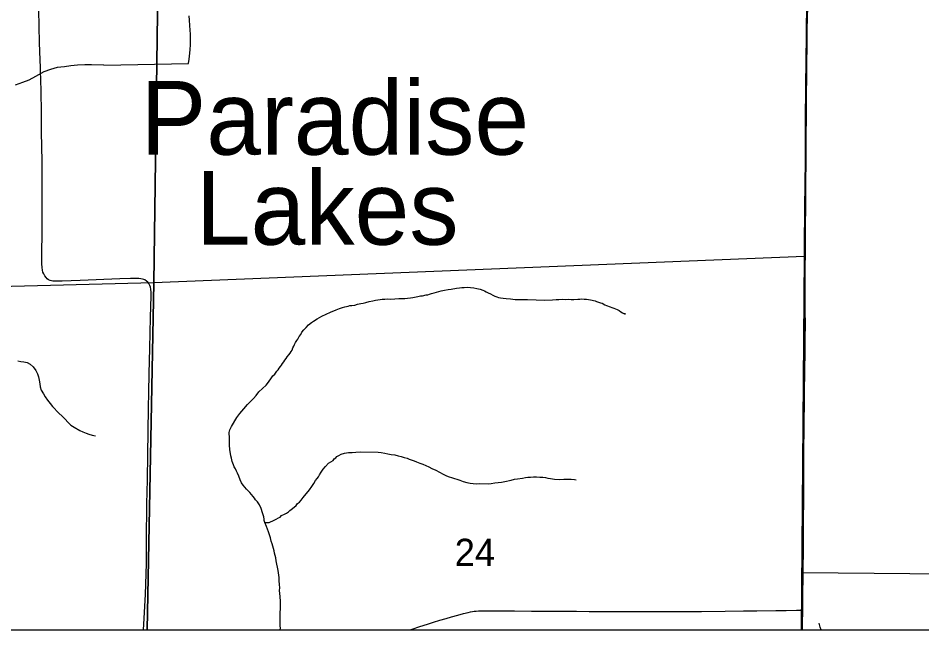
# Model space of a CAD drawing. Extents: x 0 to 34, y 0 to 22.
# Drawn here: x 29.433 to 30.131, y 13.436 to 13.908 of the extents above; entities that cross this region are included whole.
import ezdxf

# ---------------------------------------------------------------- set-up
doc = ezdxf.new("R2010")
doc.units = 0
for name, color, linetype in [('GM_X_County_Road', 7, 'Continuous'), ('GM_X_Minor_Lake_Text', 7, 'Continuous'), ('GM_X_Minor_River', 7, 'Continuous'), ('GM_X_Section', 7, 'Continuous'), ('GM_X_Section_Text', 7, 'Continuous'), ('GM_X_Township_Road', 7, 'Continuous'), ('GM_X_Unincorporated', 7, 'Continuous'), ('SC_Scratch1', 7, 'Continuous'), ('SH_Border', 7, 'Continuous'), ('SH_Cut_Line', 7, 'Continuous')]:
    doc.layers.add(name, color=color, linetype=linetype)

msp = doc.modelspace()

# ---------------------------------------------------------------- linework, layer by layer
at = {"layer": 'GM_X_County_Road'}
for points in [[(30.03851, 13.4804), (30.03866, 13.48736), (30.03866, 13.49255), (30.03877, 13.50555), (30.03886, 13.52261), (30.03893, 13.53385), (30.03897, 13.54364), (30.03899, 13.54923), (30.03899, 13.56171), (30.0391, 13.5728), (30.03925, 13.59278), (30.03934, 13.5985), (30.0394, 13.60898), (30.03929, 13.61489), (30.03938, 13.61848), (30.03951, 13.62533), (30.03957, 13.62941), (30.03979, 13.63852), (30.03987, 13.64802), (30.04002, 13.65739), (30.04002, 13.67502), (30.04001, 13.67906), (30.03998, 13.68927), (30.03996, 13.6975), (30.03994, 13.70491), (30.04005, 13.71657), (30.04007, 13.72566), (30.04009, 13.73357), (30.04013, 13.74223), (30.04024, 13.75149), (30.04032, 13.75843), (30.04052, 13.78374), (30.04071, 13.79487), (30.04069, 13.80748), (30.04078, 13.82039), (30.04082, 13.82804), (30.04091, 13.83689), (30.0411, 13.84759), (30.04105, 13.85861), (30.04119, 13.87305), (30.04123, 13.87844), (30.04146, 13.89213), (30.04159, 13.89971), (30.04185, 13.91691)], [(30.03851, 13.4804), (30.12122, 13.47968), (30.19869, 13.47902), (30.32696, 13.47856), (30.57905, 13.47654), (30.66094, 13.47675), (30.67161, 13.4767), (30.6765, 13.47718), (30.68129, 13.47801), (30.68597, 13.47965), (30.69999, 13.48655)], [(30.03819, 13.45143), (30.03817, 13.4531), (30.0382, 13.46083), (30.03831, 13.46582), (30.03846, 13.47453), (30.03851, 13.4804)], [(29.73532, 13.43613), (29.73729, 13.43678), (29.74321, 13.43875), (29.74907, 13.44065), (29.75369, 13.44211), (29.75856, 13.44356), (29.76333, 13.44496), (29.76757, 13.44619), (29.77255, 13.44761), (29.77678, 13.44875), (29.7805, 13.44967), (29.78226, 13.45007), (29.78386, 13.45037), (29.78517, 13.45055), (29.7866, 13.45072), (29.78833, 13.45082), (29.78981, 13.45088), (29.79148, 13.45095), (29.7935, 13.45095), (29.79669, 13.45096), (29.80326, 13.45091), (29.81621, 13.45081), (29.82927, 13.45072), (29.84549, 13.45062), (29.86405, 13.45051), (29.87388, 13.45042), (29.88577, 13.45032), (29.8983, 13.45027), (29.91267, 13.45026), (29.92829, 13.45031), (29.9416, 13.45036), (29.96045, 13.45043), (29.97883, 13.45057), (29.99296, 13.45076), (30.00317, 13.4509), (30.01791, 13.45111), (30.02598, 13.45124), (30.03394, 13.45137), (30.03819, 13.45143)], [(30.03797, 13.43613), (30.03799, 13.43997), (30.03819, 13.45143)]]:
    msp.add_lwpolyline(points, dxfattribs=at)
at = {"layer": 'GM_X_Minor_River'}
for points in [[(29.49915, 13.8721), (29.56469, 13.87318), (29.56512, 13.87659), (29.56557, 13.88114), (29.5658, 13.88399), (29.56605, 13.88778), (29.56617, 13.89595), (29.56583, 13.89899), (29.5657, 13.9026), (29.56538, 13.90679), (29.56505, 13.91002)], [(29.49915, 13.8721), (29.48976, 13.87236), (29.48445, 13.87232), (29.47894, 13.87209), (29.4738, 13.87148), (29.46884, 13.87067), (29.46314, 13.87026), (29.45816, 13.86869), (29.45299, 13.86674), (29.44644, 13.86332), (29.44142, 13.86042), (29.43644, 13.85866), (29.43069, 13.85654)], [(29.61678, 13.61716), (29.61894, 13.61995), (29.6244, 13.6251), (29.62558, 13.62639), (29.62677, 13.62807), (29.62815, 13.62992), (29.62973, 13.63215), (29.63129, 13.63363), (29.63288, 13.63586), (29.63386, 13.63697), (29.63466, 13.63827), (29.63564, 13.63938), (29.63643, 13.6405), (29.63723, 13.6418), (29.63822, 13.6431), (29.63901, 13.64441), (29.64, 13.64571), (29.64079, 13.64682), (29.64197, 13.64831), (29.64296, 13.64961), (29.64376, 13.65091), (29.64455, 13.65203), (29.64518, 13.65391), (29.64597, 13.65521), (29.64639, 13.65634), (29.6472, 13.65802), (29.64819, 13.65951), (29.64898, 13.66063), (29.64999, 13.6625), (29.65117, 13.66417), (29.65217, 13.66585), (29.65355, 13.66771), (29.65532, 13.66955), (29.65727, 13.67158), (29.65941, 13.67342), (29.66115, 13.6745), (29.66386, 13.67632), (29.66559, 13.67722), (29.66752, 13.6783), (29.67405, 13.68133), (29.67865, 13.68309), (29.68114, 13.68415), (29.68344, 13.68503), (29.68516, 13.68536), (29.68783, 13.68604), (29.68917, 13.68638), (29.69069, 13.68652), (29.69297, 13.68683), (29.69508, 13.68753), (29.69755, 13.68802), (29.69946, 13.68834), (29.70156, 13.68885), (29.70404, 13.68953), (29.7069, 13.69021), (29.70899, 13.69052), (29.71242, 13.69118), (29.71394, 13.69132), (29.71603, 13.69145), (29.71831, 13.69157), (29.72077, 13.6915), (29.72381, 13.69178), (29.72684, 13.69188), (29.72931, 13.692), (29.73158, 13.69193), (29.73367, 13.69224), (29.73595, 13.69255), (29.73766, 13.69269), (29.74166, 13.69333), (29.74357, 13.69384), (29.74528, 13.69398), (29.74795, 13.69466), (29.74928, 13.69481), (29.75062, 13.69515), (29.75215, 13.69567), (29.75425, 13.69636), (29.7596, 13.69772), (29.76208, 13.69841), (29.76494, 13.69889), (29.76722, 13.6992), (29.77141, 13.69983), (29.77369, 13.70014), (29.77559, 13.70046), (29.7773, 13.70041), (29.77957, 13.70053), (29.78222, 13.70045), (29.78487, 13.70018), (29.78713, 13.69973), (29.78976, 13.69908), (29.79163, 13.69846), (29.79313, 13.69784), (29.79443, 13.69704), (29.79592, 13.69624), (29.7976, 13.69543), (29.79947, 13.69461), (29.80096, 13.69381), (29.80246, 13.69319), (29.80396, 13.69276), (29.80547, 13.69253), (29.80735, 13.69228), (29.8098, 13.69183), (29.8132, 13.69153)], [(29.8132, 13.69153), (29.8166, 13.69124), (29.82266, 13.69106), (29.82626, 13.69114), (29.83951, 13.69074), (29.84557, 13.69093), (29.84842, 13.69103), (29.85051, 13.69116), (29.85297, 13.69127), (29.85524, 13.69121), (29.85771, 13.69132), (29.85998, 13.69125), (29.86206, 13.69119), (29.8651, 13.69148), (29.86661, 13.69143), (29.86757, 13.69159), (29.87003, 13.69152), (29.87172, 13.69127), (29.87343, 13.69122), (29.87494, 13.69099), (29.87832, 13.69012), (29.87944, 13.68971), (29.88094, 13.6891), (29.88263, 13.68866), (29.88375, 13.68825), (29.88599, 13.68704), (29.88711, 13.68663), (29.88992, 13.6854), (29.89142, 13.68498), (29.89273, 13.68437), (29.89404, 13.68395), (29.89554, 13.68352), (29.89703, 13.68272), (29.89832, 13.68154), (29.89963, 13.68093), (29.90149, 13.67992), (29.90152, 13.68068)], [(29.43281, 13.64369), (29.43507, 13.64324), (29.43753, 13.64299), (29.43998, 13.64254), (29.44242, 13.64133), (29.44463, 13.63917), (29.44683, 13.63645), (29.44808, 13.63376), (29.44878, 13.63146), (29.44927, 13.62897), (29.44976, 13.62611), (29.45008, 13.62382), (29.45095, 13.62114), (29.45257, 13.61824), (29.45384, 13.61593), (29.45566, 13.6134), (29.45787, 13.61087), (29.4597, 13.60854), (29.46449, 13.60347), (29.46708, 13.60111), (29.46929, 13.59877), (29.47149, 13.59643), (29.47389, 13.59408), (29.47631, 13.59249), (29.4808, 13.59009), (29.48305, 13.58908), (29.48548, 13.58787), (29.48774, 13.58723), (29.49018, 13.5864), (29.49283, 13.58595)], [(29.6353, 13.43613), (29.63551, 13.43748), (29.63538, 13.4392), (29.63544, 13.44129), (29.63533, 13.44395), (29.63542, 13.4466), (29.6355, 13.45553), (29.63558, 13.45819), (29.63532, 13.46199), (29.6352, 13.46427), (29.63489, 13.46656), (29.63495, 13.46865), (29.63485, 13.47131), (29.63455, 13.47398), (29.63444, 13.47664), (29.63385, 13.48198), (29.63317, 13.48447), (29.63286, 13.48695), (29.63237, 13.48943), (29.63187, 13.49173), (29.63155, 13.49364), (29.63104, 13.49536), (29.63072, 13.49727), (29.6302, 13.49899), (29.62969, 13.50072), (29.62917, 13.50245), (29.62848, 13.50456), (29.6278, 13.50724), (29.62643, 13.51184), (29.62466, 13.51607), (29.62343, 13.51895), (29.62291, 13.52068), (29.62294, 13.52163), (29.62261, 13.52335), (29.62177, 13.5266), (29.62054, 13.52987), (29.6193, 13.53257), (29.61785, 13.53489), (29.61638, 13.53645), (29.61548, 13.53781), (29.61438, 13.53917), (29.6131, 13.54054), (29.61182, 13.5421), (29.60926, 13.54484), (29.6067, 13.54795), (29.60543, 13.5497), (29.60436, 13.55201), (29.60331, 13.5547), (29.60243, 13.55701), (29.60154, 13.55875), (29.60083, 13.56048), (29.59993, 13.56202), (29.59941, 13.56356), (29.59869, 13.56491), (29.59835, 13.56606), (29.59768, 13.56874), (29.59735, 13.57046), (29.59703, 13.57237), (29.59654, 13.57504), (29.59628, 13.57885), (29.5962, 13.58246), (29.5961, 13.58531), (29.59597, 13.58722), (29.59601, 13.58854), (29.59645, 13.59043), (29.59705, 13.59155), (29.59786, 13.59324), (29.60185, 13.59995), (29.60422, 13.60311), (29.60718, 13.60682), (29.61012, 13.61015), (29.61266, 13.61273), (29.61481, 13.61475), (29.61678, 13.61716)], [(29.62343, 13.51895), (29.62684, 13.51904), (29.63068, 13.52082), (29.63222, 13.52173), (29.63396, 13.52262), (29.6353, 13.52315), (29.63647, 13.52445), (29.63859, 13.52552), (29.64013, 13.52623), (29.64168, 13.52733), (29.64284, 13.52824), (29.64381, 13.52897), (29.64614, 13.5308), (29.64769, 13.53208), (29.64869, 13.53357), (29.65024, 13.53485), (29.65142, 13.53634), (29.65319, 13.53837), (29.65792, 13.54431), (29.65989, 13.54691), (29.66129, 13.54914), (29.66249, 13.55139), (29.66387, 13.55305), (29.66485, 13.55416), (29.66566, 13.55585), (29.66705, 13.55789), (29.66844, 13.56013), (29.6704, 13.56235), (29.67275, 13.56475), (29.67623, 13.56692), (29.67702, 13.56804), (29.67818, 13.56895), (29.67916, 13.56987), (29.68051, 13.57078), (29.68243, 13.57167), (29.68511, 13.57254), (29.68797, 13.57302), (29.69081, 13.57313), (29.69385, 13.57341), (29.69765, 13.57368), (29.71089, 13.57328), (29.71316, 13.57302), (29.71599, 13.57255), (29.71844, 13.5721), (29.72107, 13.57164), (29.7239, 13.57117), (29.72634, 13.57053), (29.7286, 13.57008), (29.73104, 13.56924), (29.73329, 13.56861), (29.73498, 13.56799), (29.73873, 13.56673), (29.7406, 13.56592), (29.74303, 13.56489), (29.74546, 13.56406), (29.74995, 13.56202), (29.75237, 13.56081), (29.75536, 13.55939), (29.75834, 13.55778), (29.76114, 13.55636), (29.76375, 13.55514), (29.76581, 13.55432), (29.7675, 13.5537), (29.77387, 13.55161), (29.7765, 13.55077), (29.77931, 13.54992), (29.78195, 13.54946), (29.78422, 13.5492), (29.78686, 13.54893), (29.78952, 13.54904), (29.79614, 13.54884), (29.79823, 13.54916), (29.8009, 13.54965), (29.80356, 13.54995), (29.80603, 13.55025), (29.8087, 13.55074), (29.81365, 13.55173), (29.81614, 13.55241), (29.81861, 13.55272), (29.82242, 13.55336), (29.8247, 13.55367), (29.82642, 13.554), (29.8285, 13.55413), (29.83078, 13.55425), (29.83324, 13.55436), (29.8357, 13.5541), (29.83816, 13.55402), (29.84024, 13.55377), (29.84193, 13.55334), (29.844, 13.5529), (29.84701, 13.55242), (29.85099, 13.5523), (29.85421, 13.5524), (29.85705, 13.5525), (29.85989, 13.55241), (29.86254, 13.55214), (29.86367, 13.55192)], [(30.05287, 13.43613), (30.05207, 13.43831), (30.05121, 13.44137)]]:
    msp.add_lwpolyline(points, dxfattribs=at)
at = {"layer": 'GM_X_Section'}
for points in [[(29.03576, 14.24326), (29.54494, 14.23257), (29.53789, 13.70397), (29.02875, 13.69082)], [(30.04003, 13.72439), (29.53789, 13.70397), (29.54494, 14.23257), (30.04529, 14.22791)]]:
    msp.add_lwpolyline(points, close=True, dxfattribs=at)
at = {"layer": 'GM_X_Township_Road'}
msp.add_lwpolyline([(29.5298, 13.43613), (29.53001, 13.44052), (29.53134, 13.46347), (29.53212, 13.48728), (29.53214, 13.49375), (29.53215, 13.50524), (29.53254, 13.5335), (29.53288, 13.55202), (29.53322, 13.57153), (29.53372, 13.60716), (29.53398, 13.61955), (29.53422, 13.63382), (29.53462, 13.6537), (29.53533, 13.67729), (29.53588, 13.69406), (29.53585, 13.69686), (29.53561, 13.69902), (29.53526, 13.70053), (29.53473, 13.70199), (29.53395, 13.70343), (29.53308, 13.70446), (29.53218, 13.70532), (29.53082, 13.70622), (29.52999, 13.70661), (29.52897, 13.70692), (29.52774, 13.70717), (29.52635, 13.70732), (29.51989, 13.70725), (29.51148, 13.70696), (29.48085, 13.70574), (29.4672, 13.70526), (29.46473, 13.70519), (29.46132, 13.70524), (29.45997, 13.70532), (29.45887, 13.70551), (29.4577, 13.70588), (29.45659, 13.70644), (29.4556, 13.70718), (29.45473, 13.70806), (29.4536, 13.70952), (29.45284, 13.71086), (29.45224, 13.71227), (29.45183, 13.71387), (29.45157, 13.71595), (29.45146, 13.71855), (29.4515, 13.7299), (29.45161, 13.7395), (29.45163, 13.75454), (29.45155, 13.77473), (29.45167, 13.79799), (29.4511, 13.82031), (29.45105, 13.83705), (29.45085, 13.85038), (29.45054, 13.86215), (29.45047, 13.86587), (29.4503, 13.8699), (29.44982, 13.8826), (29.44956, 13.8894), (29.44933, 13.90182), (29.44884, 13.9279)], dxfattribs=at)
at = {"layer": 'GM_X_Unincorporated'}
for points in [[(29.53272, 13.43613), (30.03763, 13.43613), (30.04003, 13.72439), (29.53789, 13.70397)], [(29.0268, 13.43613), (29.53272, 13.43613), (29.53789, 13.70397), (29.02875, 13.69082)]]:
    msp.add_lwpolyline(points, close=True, dxfattribs=at)
at = {"layer": 'SC_Scratch1'}
msp.add_line((1.5, 13.43613), (32, 13.43613), dxfattribs=at)
for points in [[(27.02715, 13.43613), (30.0382, 13.43613), (30.03824, 13.44026), (30.03835, 13.45173), (30.03836, 13.4534), (30.03843, 13.46109), (30.03851, 13.46619), (30.03863, 13.47481), (30.03872, 13.48064), (30.03882, 13.48765), (30.03886, 13.49285), (30.03897, 13.50574), (30.03911, 13.52292), (30.03917, 13.53413), (30.03922, 13.54385), (30.03923, 13.54669), (30.03924, 13.54952), (30.0393, 13.56198), (30.03935, 13.57315), (30.03951, 13.59307), (30.03955, 13.59874), (30.03968, 13.60933), (30.03974, 13.61425), (30.03975, 13.61522), (30.03979, 13.61881), (30.03988, 13.62564), (30.03993, 13.62973), (30.04004, 13.63887), (30.04015, 13.6483), (30.04022, 13.65393), (30.04026, 13.65768), (30.04041, 13.67515), (30.04039, 13.67938), (30.04034, 13.68963), (30.0403, 13.69785), (30.04026, 13.70521), (30.04034, 13.71686), (30.0404, 13.7259), (30.04046, 13.73379), (30.04052, 13.74236), (30.0406, 13.75174), (30.04066, 13.75867), (30.04089, 13.78407), (30.04097, 13.79514), (30.04107, 13.80779), (30.04116, 13.82068), (30.0412, 13.82843), (30.04126, 13.83714), (30.04131, 13.84791), (30.0414, 13.85888), (30.04152, 13.87342), (30.04154, 13.87604), (30.04157, 13.87866), (30.0418, 13.89266), (30.04192, 13.89997), (30.04223, 13.91705)], [(30.04223, 13.91705), (30.04192, 13.89997), (30.0418, 13.89266), (30.04157, 13.87866), (30.04154, 13.87604), (30.04152, 13.87342), (30.0414, 13.85888), (30.04131, 13.84791), (30.04126, 13.83714), (30.0412, 13.82843), (30.04116, 13.82068), (30.04107, 13.80779), (30.04097, 13.79514), (30.04089, 13.78407), (30.04066, 13.75867), (30.0406, 13.75174), (30.04052, 13.74236), (30.04046, 13.73379), (30.0404, 13.7259), (30.04034, 13.71686), (30.04026, 13.70521), (30.0403, 13.69785), (30.04034, 13.68963), (30.04039, 13.67938), (30.04041, 13.67515), (30.04026, 13.65768), (30.04022, 13.65393), (30.04015, 13.6483), (30.04004, 13.63887), (30.03993, 13.62973), (30.03988, 13.62564), (30.03979, 13.61881), (30.03975, 13.61522), (30.03974, 13.61425), (30.03968, 13.60933), (30.03955, 13.59874), (30.03951, 13.59307), (30.03935, 13.57315), (30.0393, 13.56198), (30.03924, 13.54952), (30.03923, 13.54669), (30.03922, 13.54385), (30.03917, 13.53413), (30.03911, 13.52292), (30.03897, 13.50574), (30.03886, 13.49285), (30.03882, 13.48765), (30.03872, 13.48064), (30.03863, 13.47481), (30.03851, 13.46619), (30.03843, 13.46109), (30.03836, 13.4534), (30.03835, 13.45173), (30.03824, 13.44026), (30.0382, 13.43613), (30.69999, 13.43613)]]:
    msp.add_lwpolyline(points, dxfattribs=at)
at = {"layer": 'SH_Border'}
msp.add_lwpolyline([(23.89999, 20.23613), (23.89999, 13.43613), (30.69999, 13.43613), (30.69999, 20.23613)], close=True, dxfattribs=at)
at = {"layer": 'SH_Cut_Line'}
for points in [[(23.89999, 13.43613), (30.0382, 13.43613), (30.03824, 13.44026), (30.03835, 13.45173), (30.03836, 13.4534), (30.03843, 13.46109), (30.03851, 13.46619), (30.03863, 13.47481), (30.03872, 13.48064), (30.03882, 13.48765), (30.03886, 13.49285), (30.03897, 13.50574), (30.03911, 13.52292), (30.03917, 13.53413), (30.03922, 13.54385), (30.03923, 13.54669), (30.03924, 13.54952), (30.0393, 13.56198), (30.03935, 13.57315), (30.03951, 13.59307), (30.03955, 13.59874), (30.03968, 13.60933), (30.03974, 13.61425), (30.03975, 13.61522), (30.03979, 13.61881), (30.03988, 13.62564), (30.03993, 13.62973), (30.04004, 13.63887), (30.04015, 13.6483), (30.04022, 13.65393), (30.04026, 13.65768), (30.04041, 13.67515), (30.04039, 13.67938), (30.04034, 13.68963), (30.0403, 13.69785), (30.04026, 13.70521), (30.04034, 13.71686), (30.0404, 13.7259), (30.04046, 13.73379), (30.04052, 13.74236), (30.0406, 13.75174), (30.04066, 13.75867), (30.04089, 13.78407), (30.04097, 13.79514), (30.04107, 13.80779), (30.04116, 13.82068), (30.0412, 13.82843), (30.04126, 13.83714), (30.04131, 13.84791), (30.0414, 13.85888), (30.04152, 13.87342), (30.04154, 13.87604), (30.04157, 13.87866), (30.0418, 13.89266), (30.04192, 13.89997), (30.04223, 13.91705)], [(30.04223, 13.91705), (30.04192, 13.89997), (30.0418, 13.89266), (30.04157, 13.87866), (30.04154, 13.87604), (30.04152, 13.87342), (30.0414, 13.85888), (30.04131, 13.84791), (30.04126, 13.83714), (30.0412, 13.82843), (30.04116, 13.82068), (30.04107, 13.80779), (30.04097, 13.79514), (30.04089, 13.78407), (30.04066, 13.75867), (30.0406, 13.75174), (30.04052, 13.74236), (30.04046, 13.73379), (30.0404, 13.7259), (30.04034, 13.71686), (30.04026, 13.70521), (30.0403, 13.69785), (30.04034, 13.68963), (30.04039, 13.67938), (30.04041, 13.67515), (30.04026, 13.65768), (30.04022, 13.65393), (30.04015, 13.6483), (30.04004, 13.63887), (30.03993, 13.62973), (30.03988, 13.62564), (30.03979, 13.61881), (30.03975, 13.61522), (30.03974, 13.61425), (30.03968, 13.60933), (30.03955, 13.59874), (30.03951, 13.59307), (30.03935, 13.57315), (30.0393, 13.56198), (30.03924, 13.54952), (30.03923, 13.54669), (30.03922, 13.54385), (30.03917, 13.53413), (30.03911, 13.52292), (30.03897, 13.50574), (30.03886, 13.49285), (30.03882, 13.48765), (30.03872, 13.48064), (30.03863, 13.47481), (30.03851, 13.46619), (30.03843, 13.46109), (30.03836, 13.4534), (30.03835, 13.45173), (30.03824, 13.44026), (30.0382, 13.43613), (30.69999, 13.43613)]]:
    msp.add_lwpolyline(points, dxfattribs=at)

# ---------------------------------------------------------------- texts
at = {"layer": 'GM_X_Minor_Lake_Text'}
for s, rotation, p in [('Paradise', 0.00173, (29.52764, 13.80291)), ('Lakes', 0.00169, (29.57028, 13.73343))]:
    msp.add_text(s, height=0.056816, rotation=rotation, dxfattribs=at).set_placement(p)
at = {"layer": 'GM_X_Section_Text'}
msp.add_text('24', height=0.020928, rotation=0.00001, dxfattribs=at).set_placement((29.77007, 13.48556))

doc.saveas('drawing.dxf')
